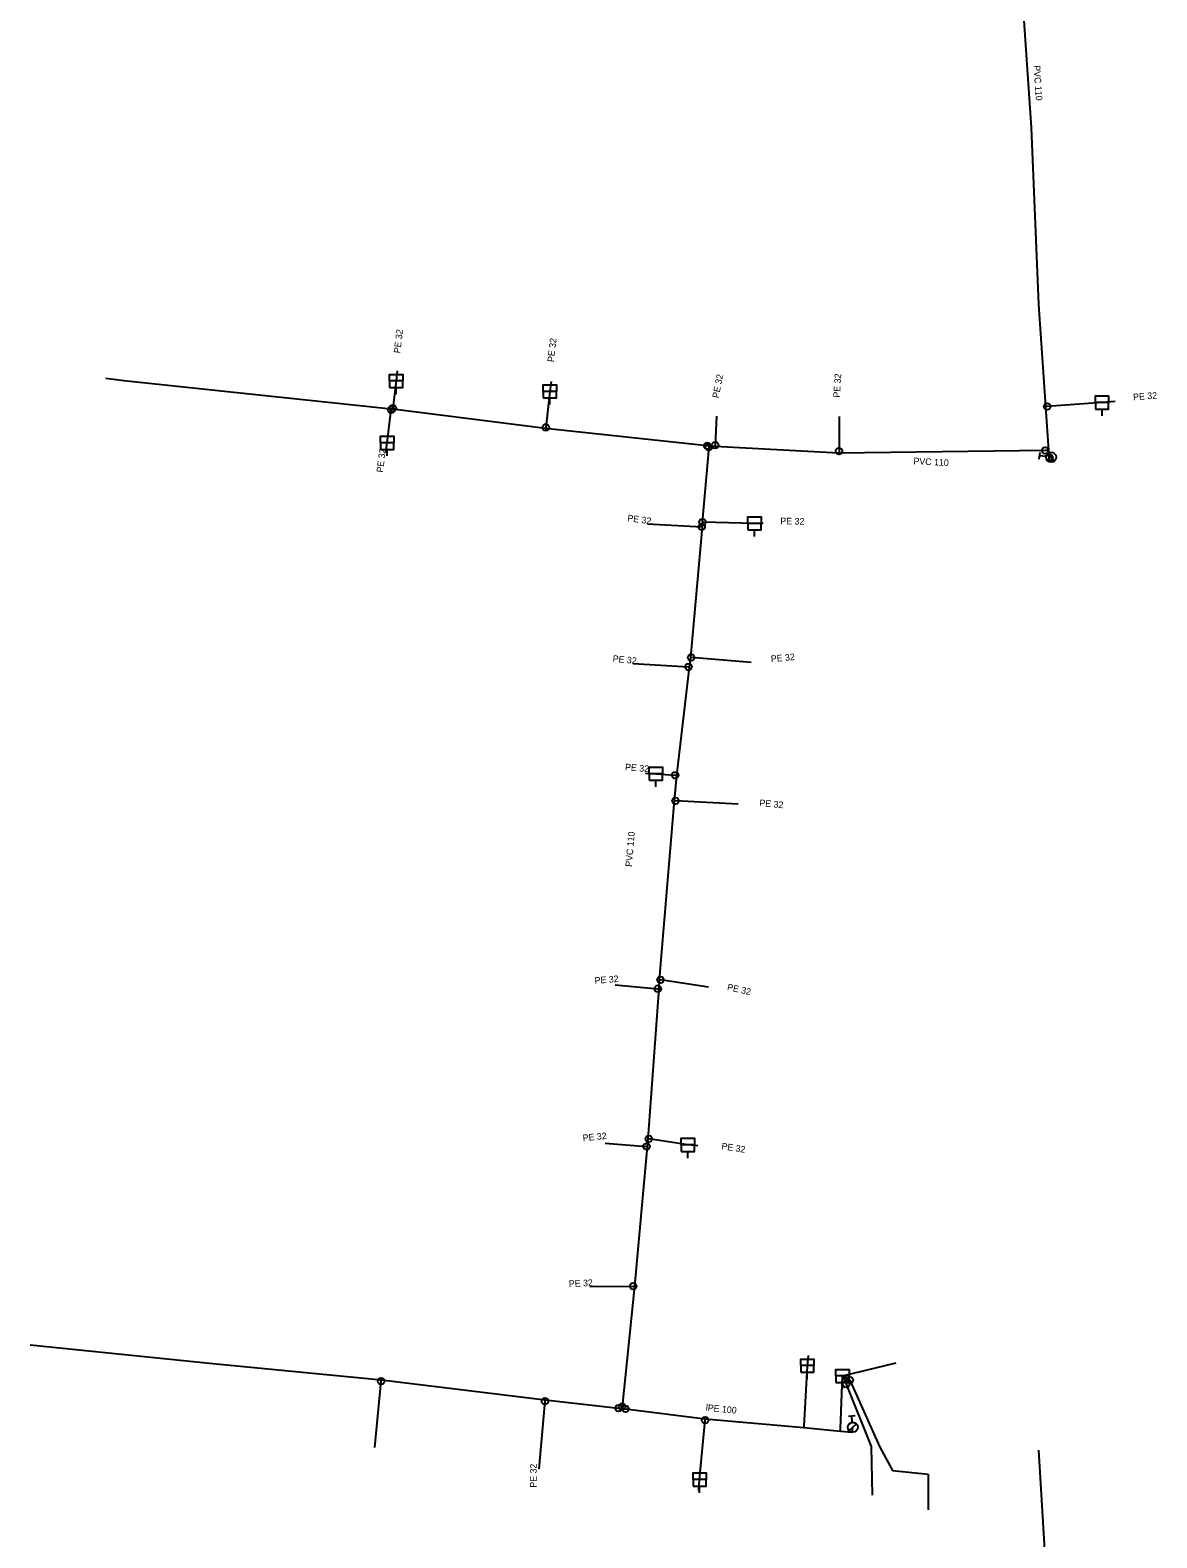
# Model space of a CAD drawing. Extents: x -725126 to -724740, y -1049524 to -1048684.
# Drawn here: x -725061.6 to -724890.6, y -1049327.5 to -1049098.7 of the extents above; entities that cross this region are included whole.
import ezdxf

# ---------------------------------------------------------------- set-up
doc = ezdxf.new("R2010")
doc.units = 0
doc.layers.add('Level 0', color=7, linetype='Continuous')

msp = doc.modelspace()

# ---------------------------------------------------------------- linework, layer by layer
at = {"layer": 'Level 0'}
for p, q in [((-724911.14, -1049092.83), (-724909.72, -1049113.49)), ((-724909.72, -1049113.49), (-724908.59, -1049140.34)), ((-724908.59, -1049140.34), (-724907.54, -1049155.83)), ((-725005.96, -1049150.41), (-725006.08, -1049151.95)), ((-725047.4, -1049151.92), (-725050.13, -1049151.58)), ((-725006.85, -1049156.21), (-725047.4, -1049151.92)), ((-725006.08, -1049151.95), (-725006.58, -1049156.06)), ((-725006.08, -1049153.95), (-725006.08, -1049152.95)), ((-724982.59, -1049152.03), (-724982.77, -1049153.53)), ((-724982.77, -1049153.53), (-724983.38, -1049158.99)), ((-724982.77, -1049155.53), (-724982.77, -1049154.53)), ((-724898.96, -1049155.22), (-724907.29, -1049155.81)), ((-724896.96, -1049155.08), (-724898.96, -1049155.22)), ((-725007.47, -1049161.33), (-725006.86, -1049156.32)), ((-725006.86, -1049156.32), (-725006.85, -1049156.21)), ((-725006.61, -1049156.23), (-725006.85, -1049156.21)), ((-725006.58, -1049156.06), (-725006.61, -1049156.23)), ((-724983.41, -1049159.19), (-725006.61, -1049156.23)), ((-724957.46, -1049157.29), (-724957.69, -1049161.68)), ((-724938.87, -1049157.32), (-724938.88, -1049162.59)), ((-724907.29, -1049155.81), (-724907.54, -1049155.83)), ((-724907.54, -1049155.83), (-724907.08, -1049162.48)), ((-724898.96, -1049157.22), (-724898.96, -1049156.22)), ((-724983.38, -1049158.99), (-724983.41, -1049159.19)), ((-724958.87, -1049161.79), (-724983.41, -1049159.19)), ((-725007.68, -1049162.81), (-725007.47, -1049161.33)), ((-725007.47, -1049163.33), (-725007.47, -1049162.33)), ((-724958.66, -1049162.01), (-724959.64, -1049173.4)), ((-724958.63, -1049161.82), (-724958.87, -1049161.79)), ((-724958.63, -1049161.82), (-724958.66, -1049162.01)), ((-724957.73, -1049161.88), (-724958.63, -1049161.82)), ((-724957.69, -1049161.68), (-724957.73, -1049161.88)), ((-724938.9, -1049162.91), (-724957.73, -1049161.88)), ((-724907.59, -1049162.5), (-724938.9, -1049162.91)), ((-724938.88, -1049162.59), (-724938.9, -1049162.91)), ((-724908.49, -1049163.81), (-724908.37, -1049162.82)), ((-724907.43, -1049163.43), (-724908.43, -1049163.31)), ((-724907.08, -1049162.48), (-724907.59, -1049162.5)), ((-724907.08, -1049162.48), (-724907.02, -1049163.56)), ((-724906.3, -1049164.16), (-724907.08, -1049162.88)), ((-724907.02, -1049163.56), (-724906.94, -1049163.55)), ((-724907.02, -1049163.56), (-724907, -1049164.01)), ((-724906.94, -1049163.55), (-724906.69, -1049163.52)), ((-724967.95, -1049173.62), (-724959.72, -1049174.08)), ((-724959.64, -1049173.4), (-724959.65, -1049174.09)), ((-724959.61, -1049173.4), (-724959.64, -1049173.4)), ((-724951.72, -1049173.56), (-724959.61, -1049173.4)), ((-724950.4, -1049173.58), (-724951.72, -1049173.56)), ((-724959.65, -1049174.09), (-724961.42, -1049193.94)), ((-724959.72, -1049174.08), (-724959.65, -1049174.09)), ((-724951.72, -1049175.56), (-724951.72, -1049174.56)), ((-724961.42, -1049193.94), (-724961.64, -1049195.37)), ((-724961.31, -1049193.93), (-724961.42, -1049193.94)), ((-724952.2, -1049194.66), (-724961.31, -1049193.93)), ((-724970.11, -1049194.81), (-724961.74, -1049195.36)), ((-724961.64, -1049195.37), (-724963.52, -1049211.81)), ((-724961.74, -1049195.36), (-724961.64, -1049195.37)), ((-724968.23, -1049211.45), (-724966.67, -1049211.56)), ((-724966.67, -1049211.56), (-724963.73, -1049211.8)), ((-724966.67, -1049213.56), (-724966.67, -1049212.56)), ((-724963.52, -1049211.81), (-724963.9, -1049215.64)), ((-724963.73, -1049211.8), (-724963.52, -1049211.81)), ((-724963.9, -1049215.64), (-724966.17, -1049242.79)), ((-724963.69, -1049215.66), (-724963.9, -1049215.64)), ((-724954.18, -1049216.2), (-724963.69, -1049215.66)), ((-724972.86, -1049243.61), (-724966.37, -1049244.18)), ((-724966.25, -1049244.17), (-724967.89, -1049266.96)), ((-724966.37, -1049244.18), (-724966.25, -1049244.17)), ((-724966.17, -1049242.79), (-724966.25, -1049244.17)), ((-724965.99, -1049242.83), (-724966.17, -1049242.79)), ((-724958.71, -1049243.93), (-724965.99, -1049242.83)), ((-724967.89, -1049266.96), (-724967.98, -1049268.14)), ((-724967.76, -1049266.97), (-724967.89, -1049266.96)), ((-724961.82, -1049267.88), (-724967.76, -1049266.97)), ((-724974.36, -1049267.65), (-724968.08, -1049268.15)), ((-724967.98, -1049268.14), (-724969.9, -1049289.32)), ((-724968.08, -1049268.15), (-724967.98, -1049268.14)), ((-724960.32, -1049268.05), (-724961.82, -1049267.88)), ((-724961.82, -1049269.88), (-724961.82, -1049268.88)), ((-724976.69, -1049289.38), (-724970.11, -1049289.33)), ((-724969.9, -1049289.32), (-724971.81, -1049307.62)), ((-724970.11, -1049289.33), (-724969.9, -1049289.32)), ((-725061.64, -1049298.21), (-725033.89, -1049301.08)), ((-725033.89, -1049301.08), (-725008.33, -1049303.55)), ((-724943.7, -1049301.4), (-724944.2, -1049310.56)), ((-724943.57, -1049299.85), (-724943.7, -1049301.4)), ((-724938.34, -1049302.96), (-724930.22, -1049300.96)), ((-725009.32, -1049313.8), (-725008.36, -1049303.76)), ((-725008.36, -1049303.76), (-725008.33, -1049303.55)), ((-725008.33, -1049303.55), (-724983.5, -1049306.56)), ((-724943.7, -1049303.39), (-724943.7, -1049302.39)), ((-724938.65, -1049310.99), (-724938.34, -1049302.96)), ((-724938.34, -1049302.96), (-724937.38, -1049303.48)), ((-724938.34, -1049302.96), (-724937.87, -1049304.02)), ((-724938.34, -1049304.96), (-724938.34, -1049303.96)), ((-724937.87, -1049304.02), (-724937.81, -1049304.2)), ((-724937.81, -1049304.2), (-724934, -1049313.64)), ((-724937.38, -1049303.48), (-724937.22, -1049303.6)), ((-724937.22, -1049303.6), (-724932.72, -1049313.67)), ((-724984.41, -1049317.03), (-724983.5, -1049306.77)), ((-724983.5, -1049306.77), (-724983.5, -1049306.56)), ((-724983.5, -1049306.56), (-724972.33, -1049307.83)), ((-724972.33, -1049307.83), (-724971.84, -1049307.89)), ((-724971.81, -1049307.62), (-724971.84, -1049307.89)), ((-724971.84, -1049307.89), (-724971.27, -1049307.96)), ((-724971.27, -1049307.96), (-724959.18, -1049309.45)), ((-724960.04, -1049318.67), (-724959.19, -1049309.66)), ((-724959.19, -1049309.66), (-724959.18, -1049309.45)), ((-724959.18, -1049309.45), (-724944.23, -1049310.76)), ((-724944.2, -1049310.56), (-724944.23, -1049310.76)), ((-724944.23, -1049310.76), (-724938.67, -1049311.31)), ((-724938.67, -1049311.31), (-724938.65, -1049310.99)), ((-724937.45, -1049309.04), (-724936.45, -1049308.95)), ((-724937.33, -1049311.25), (-724936.24, -1049310.22)), ((-724936.86, -1049309.99), (-724936.95, -1049309)), ((-724936.86, -1049311.49), (-724936.79, -1049310.74)), ((-724938.67, -1049311.31), (-724936.86, -1049311.49)), ((-724934, -1049313.64), (-724933.87, -1049321.03)), ((-724932.72, -1049313.67), (-724930.76, -1049317.31)), ((-724905.3, -1049367.83), (-724908.57, -1049314.24)), ((-724930.76, -1049317.31), (-724925.37, -1049317.85)), ((-724925.37, -1049317.85), (-724925.35, -1049323.27)), ((-724960.18, -1049320.32), (-724960.04, -1049318.67)), ((-724960.04, -1049320.67), (-724960.04, -1049319.67))]:
    msp.add_line(p, q, dxfattribs=at)
for points in [[(-725007.08, -1049151.95), (-725007.08, -1049150.95), (-725005.08, -1049150.95), (-725005.08, -1049151.95)], [(-724983.77, -1049153.53), (-724983.77, -1049152.53), (-724981.77, -1049152.53), (-724981.77, -1049153.53)], [(-724899.96, -1049155.22), (-724899.96, -1049154.22), (-724897.96, -1049154.22), (-724897.96, -1049155.22)], [(-725008.47, -1049161.33), (-725008.47, -1049160.33), (-725006.47, -1049160.33), (-725006.47, -1049161.33)], [(-724952.72, -1049173.56), (-724952.72, -1049172.56), (-724950.72, -1049172.56), (-724950.72, -1049173.56)], [(-724967.67, -1049211.56), (-724967.67, -1049210.56), (-724965.67, -1049210.56), (-724965.67, -1049211.56)], [(-724962.82, -1049267.88), (-724962.82, -1049266.88), (-724960.82, -1049266.88), (-724960.82, -1049267.88)], [(-724944.7, -1049301.39), (-724944.7, -1049300.39), (-724942.7, -1049300.39), (-724942.7, -1049301.39)], [(-724939.34, -1049302.96), (-724939.34, -1049301.96), (-724937.34, -1049301.96), (-724937.34, -1049302.96)], [(-724961.04, -1049318.67), (-724961.04, -1049317.67), (-724959.04, -1049317.67), (-724959.04, -1049318.67)]]:
    msp.add_lwpolyline(points, dxfattribs=at)
for points in [[(-725007.08, -1049152.95), (-725005.08, -1049152.95), (-725005.08, -1049151.95), (-725007.08, -1049151.95)], [(-724983.77, -1049154.53), (-724981.77, -1049154.53), (-724981.77, -1049153.53), (-724983.77, -1049153.53)], [(-724899.96, -1049156.22), (-724897.96, -1049156.22), (-724897.96, -1049155.22), (-724899.96, -1049155.22)], [(-725008.47, -1049162.33), (-725006.47, -1049162.33), (-725006.47, -1049161.33), (-725008.47, -1049161.33)], [(-724952.72, -1049174.56), (-724950.72, -1049174.56), (-724950.72, -1049173.56), (-724952.72, -1049173.56)], [(-724967.67, -1049212.56), (-724965.67, -1049212.56), (-724965.67, -1049211.56), (-724967.67, -1049211.56)], [(-724962.82, -1049268.88), (-724960.82, -1049268.88), (-724960.82, -1049267.88), (-724962.82, -1049267.88)], [(-724944.7, -1049302.39), (-724942.7, -1049302.39), (-724942.7, -1049301.39), (-724944.7, -1049301.39)], [(-724939.34, -1049303.96), (-724937.34, -1049303.96), (-724937.34, -1049302.96), (-724939.34, -1049302.96)], [(-724961.04, -1049319.67), (-724959.04, -1049319.67), (-724959.04, -1049318.67), (-724961.04, -1049318.67)]]:
    msp.add_lwpolyline(points, close=True, dxfattribs=at)
for centre, radius in [((-724907.29, -1049155.81), 0.5), ((-725006.86, -1049156.32), 0.5), ((-725006.58, -1049156.06), 0.5), ((-724983.38, -1049158.99), 0.5), ((-724958.87, -1049161.79), 0.5), ((-724958.66, -1049162.01), 0.5), ((-724957.69, -1049161.68), 0.5), ((-724938.88, -1049162.59), 0.5), ((-724907.59, -1049162.5), 0.5), ((-724906.69, -1049163.52), 0.75), ((-724906.94, -1049163.55), 0.5), ((-724959.72, -1049174.08), 0.5), ((-724959.61, -1049173.4), 0.5), ((-724961.31, -1049193.93), 0.5), ((-724961.74, -1049195.36), 0.5), ((-724963.73, -1049211.8), 0.5), ((-724963.69, -1049215.66), 0.5), ((-724965.99, -1049242.83), 0.5), ((-724966.37, -1049244.18), 0.5), ((-724967.76, -1049266.97), 0.5), ((-724968.08, -1049268.15), 0.5), ((-724970.11, -1049289.33), 0.5), ((-725008.36, -1049303.76), 0.5), ((-724937.81, -1049304.2), 0.5), ((-724937.22, -1049303.6), 0.5), ((-724983.5, -1049306.77), 0.5), ((-724972.33, -1049307.83), 0.5), ((-724971.81, -1049307.62), 0.5), ((-724971.27, -1049307.96), 0.5), ((-724959.19, -1049309.66), 0.5), ((-724936.79, -1049310.74), 0.75)]:
    msp.add_circle(centre, radius, dxfattribs=at)

# ---------------------------------------------------------------- texts
for s, rotation, p in [('PVC 110', 273.932, (-724909.36, -1049104.09)), ('PE 32', 83.064, (-725005.48, -1049147.79)), ('PE 32', 83.625, (-724982.15, -1049149.12)), ('PE 32', 86.424, (-724938.76, -1049154.5)), ('PE 32', 78.69, (-724957.15, -1049154.61)), ('PE 32', 4.051, (-724894.21, -1049154.88)), ('PE 32', 83.058, (-725008.09, -1049165.89)), ('PVC 110', 356.869, (-724927.6, -1049164.58)), ('PE 32', 351.87, (-724971.05, -1049173.21)), ('PE 32', 358.838, (-724947.79, -1049173.69)), ('PE 32', 354.289, (-724973.26, -1049194.56)), ('PE 32', 5.194, (-724949.18, -1049194.63)), ('PE 32', 355.333, (-724971.38, -1049211.02)), ('PE 32', 354.56, (-724951, -1049216.46)), ('PVC 110', 85.221, (-724970.32, -1049225.72)), ('PE 32', 4.764, (-724975.93, -1049243.46)), ('PE 32', 347.471, (-724955.92, -1049244.38)), ('PE 32', 5.711, (-724977.73, -1049267.34)), ('PE 32', 351.29, (-724956.77, -1049268.54)), ('PE 32', 2.726, (-724979.86, -1049289.46)), ('lPE 100', 354.351, (-724959.13, -1049308.22)), ('PE 32', 90, (-724984.77, -1049319.91))]:
    msp.add_text(s, height=1, rotation=rotation, dxfattribs=at).set_placement(p)

doc.saveas('drawing.dxf')
